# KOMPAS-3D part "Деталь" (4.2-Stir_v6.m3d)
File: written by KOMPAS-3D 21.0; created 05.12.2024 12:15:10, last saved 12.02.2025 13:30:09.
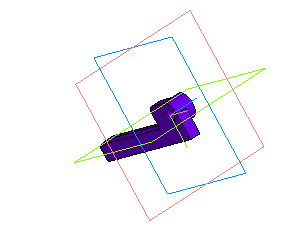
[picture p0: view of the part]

Document properties: Автор: Admin; Полное имя файла: Z:\!_Силкин\!!!_Дрон\Autel Robotics EVO Lite\Подвес\EVO\V6\под\под\4.2-Stir_v6.m3d

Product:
- Part/product: Деталь
    Масса: 0.015288
  - Body: Тело 1
      Масса: 0.014102

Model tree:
1. Эскиз:1
2. Элемент выдавливания:1
     Расстояние 1 = 4
3. Эскиз:2  (with: Элемент выдавливания:1)
4. Элемент выдавливания:2
     Расстояние 2 = 7
5. Элемент выдавливания:3  (with: Элемент выдавливания:1)
     Расстояние 2 = 5
6. Эскиз:5  (with: Элемент выдавливания:3)
7. Элемент выдавливания:5
     Расстояние 1 = 5; Расстояние 2 = 48
8. Эскиз:6  (with: Элемент выдавливания:1, Элемент выдавливания:5)
9. Элемент выдавливания:6
     Расстояние 2 = 10
10. Скругление:3  (with: Элемент выдавливания:5, Элемент выдавливания:6)
     Радиус = 1
11. Скругление:4  (with: Элемент выдавливания:5)
     Радиус = 0.5
12. Эскиз:7  (with: Элемент выдавливания:1)
13. Элемент выдавливания:7  (with: Элемент выдавливания:1)
     Расстояние 1 = -4
14. Фаска:1  (with: Элемент выдавливания:1)
     Угол = 45; Длина 1 = 0.5; Длина 2 = 0.5
15. Эскиз:8  (with: Элемент выдавливания:2)
16. Элемент выдавливания:8
     Расстояние 2 = 10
